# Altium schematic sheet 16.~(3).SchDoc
size 398 x 287 mm
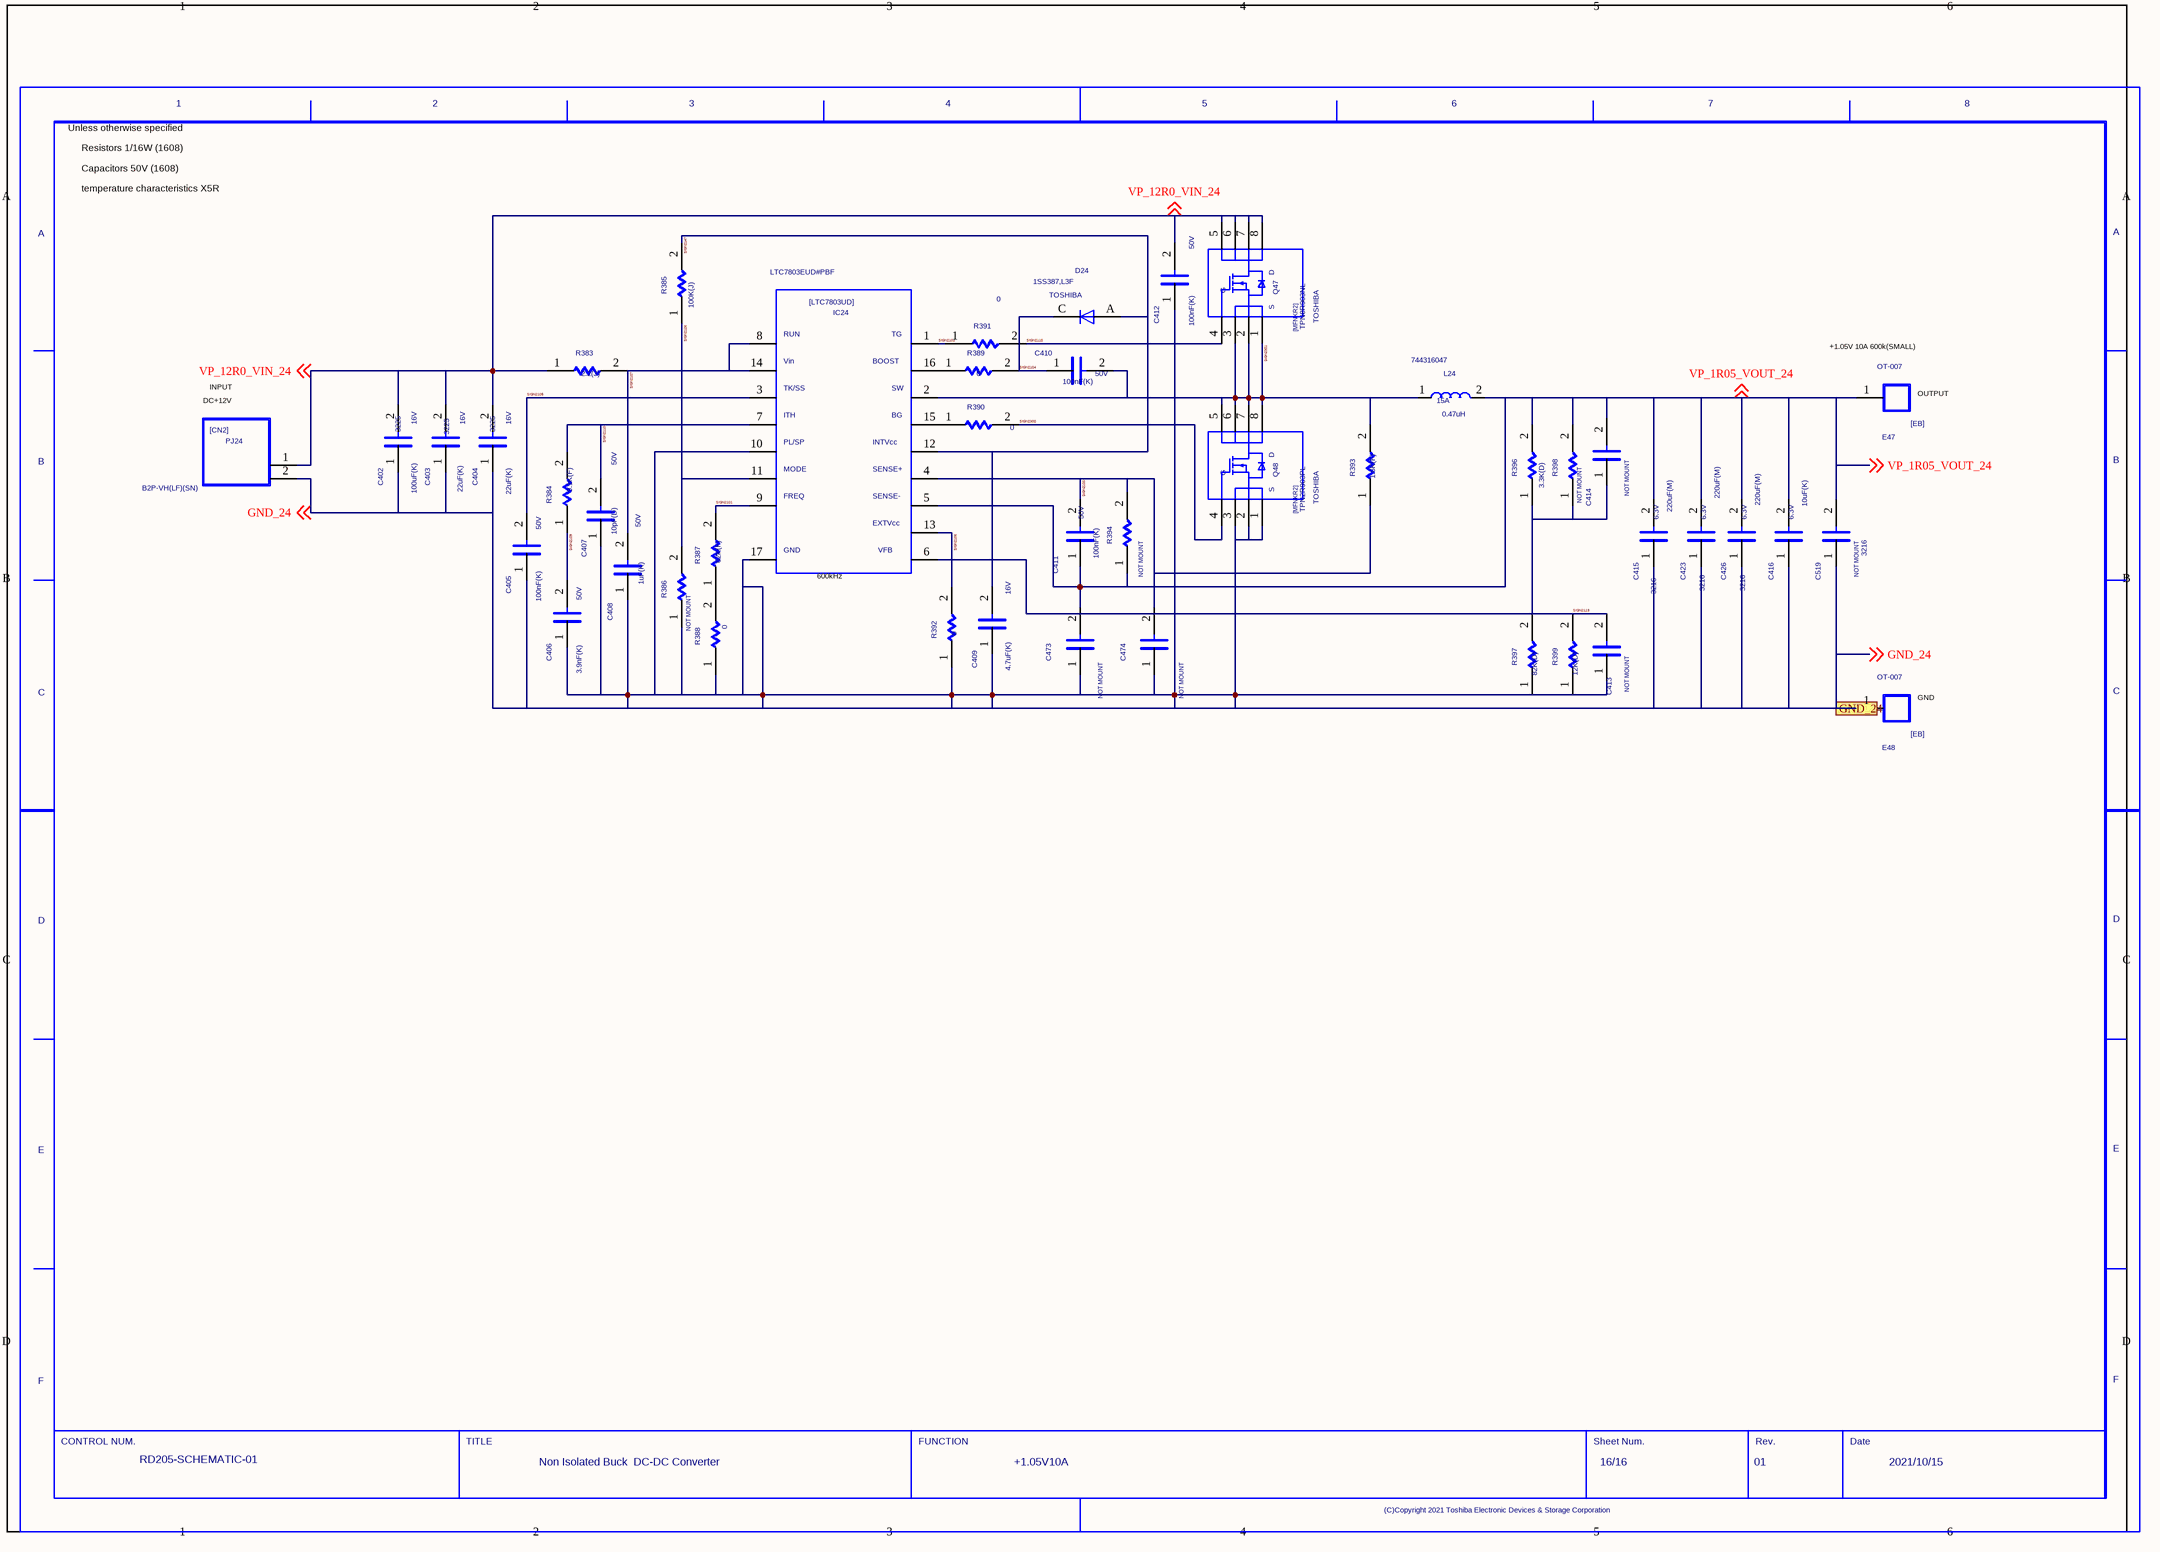
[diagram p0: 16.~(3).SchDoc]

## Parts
C402  SIZECODESMD: 3225  VAL2: 16V  VAL1: 100uF(K)  (hidden comment: C)
C403  SIZECODESMD: 3225  VAL2: 16V  VAL1: 22uF(K)  (hidden comment: C)
C404  SIZECODESMD: 3225  VAL2: 16V  VAL1: 22uF(K)  (hidden comment: C)
C405  VAL2: 50V  VAL1: 100nF(K)  (hidden comment: C)
C406  VAL2: 50V  VAL1: 3.9nF(K)  (hidden comment: C)
C407  VAL2: 50V  VAL1: 10pF(D)  (hidden comment: C)
C408  VAL2: 50V  VAL1: 1uF(K)  (hidden comment: C)
C409  VAL2: 16V  VAL1: 4.7uF(K)  (hidden comment: C)
C410  VAL2: 50V  VAL1: 100nF(K)  (hidden comment: C)
C411  VAL2: 50V  VAL1: 100nF(K)  (hidden comment: C)
C412  VAL2: 50V  VAL1: 100nF(K)  (hidden comment: C)
C413  NOTMOUNT: NOT MOUNT  (hidden comment: C)
C414  NOTMOUNT: NOT MOUNT  (hidden comment: C)
C415  SIZECODESMD: 3216  VAL2: 6.3V  VAL1: 220uF(M)  (hidden comment: C)
C416  VAL2: 6.3V  VAL1: 10uF(K)  (hidden comment: C)
C423  SIZECODESMD: 3216  VAL2: 6.3V  VAL1: 220uF(M)  (hidden comment: C)
C426  SIZECODESMD: 3216  VAL2: 6.3V  VAL1: 220uF(M)  (hidden comment: C)
C473  NOTMOUNT: NOT MOUNT  (hidden comment: C)
C474  NOTMOUNT: NOT MOUNT  (hidden comment: C)
C519  NOTMOUNT: NOT MOUNT  SIZECODESMD: 3216  (hidden comment: C)
D24  USERCOMPTEXT3: TOSHIBA  VAL3: 1SS387,L3F  (hidden comment: D)
E47  VAL3: OT-007  (hidden comment: EB)
E48  VAL3: OT-007  (hidden comment: EB)
IC24  VAL3: LTC7803EUD#PBF  (hidden comment: LTC7803UD)
L24  VAL3: 744316047  VAL2: 15A  VAL1: 0.47uH  (hidden comment: L)
PJ24  VAL3: B2P-VH(LF)(SN)  (hidden comment: CN2)
Q47  USERCOMPTEXT3: TOSHIBA  VAL3: TPN8R903NL  (hidden comment: MFNKR2)
Q48  USERCOMPTEXT3: TOSHIBA  VAL3: TPN2R903PL  (hidden comment: MFNKR2)
R383  VAL1: 2.2(J)  (hidden comment: R)
R384  VAL1: 9.1K(F)  (hidden comment: R)
R385  VAL1: 100K(J)  (hidden comment: R)
R386  NOTMOUNT: NOT MOUNT  (hidden comment: R)
R387  VAL1: 62K(F)  (hidden comment: R)
R388  VAL1: 0  (hidden comment: R)
R389  VAL1: 0  (hidden comment: R)
R390  VAL1: 0  (hidden comment: R)
R391  VAL1: 0  (hidden comment: R)
R392  VAL1: 0  (hidden comment: R)
R393  VAL1: 1.6K(F)  (hidden comment: R)
R394  NOTMOUNT: NOT MOUNT  (hidden comment: R)
R396  VAL1: 3.3K(D)  (hidden comment: R)
R397  VAL1: 82K(D)  (hidden comment: R)
R398  NOTMOUNT: NOT MOUNT  (hidden comment: R)
R399  VAL1: 12K(D)  (hidden comment: R)
U?  DATE: 2021/10/15  SHEETNUMBER: 16/16  TITLE: Non Isolated Buck / DC-DC Converter  REVISION: 01  DRAWINGNUMBER: RD205-SCHEMATIC-01  FUNCTION: +1.05V10A  (hidden comment: WAKU_DEF100)

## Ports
GND_24

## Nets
GND_24: C402.1 C403.1 C404.1 C405.1 C406.1 C407.1 C408.1 C409.1 C412.1 C413.1 C415.1 C416.1 C423.1 C426.1 C473.1 C474.1 C519.1 E48.1 IC24.10 IC24.17 PJ24.2 Q48.1 Q48.2 Q48.3 R386.1 R388.1 R392.1 R397.1 R399.1 ; off-sheet GND_24, port GND_24
SIGN2100: C411.2 C474.2 IC24.4 R393.1 R394.2
SIGN2101: IC24.9 R387.2
SIGN2103: IC24.1 R391.1
SIGN2104: C410.1 D24.C R389.2
SIGN2105: C405.2 IC24.3
SIGN2106: IC24.13 R392.2
SIGN2107: C408.2 IC24.8 IC24.14 R383.2
SIGN2109: C406.2 R384.1
SIGN2110: C407.2 IC24.7 R384.2
SIGN2113: C413.2 C414.1 IC24.6 R396.1 R397.2 R398.1 R399.2
SIGN2115: Q47.4 R391.2
SIGN2126: IC24.11 R385.1 R386.2
SIGN2147: C409.2 D24.A IC24.12 R385.2
SIGN2300: Q48.4 R390.2
SIGN2301: C410.2 IC24.2 L24.1 Q47.1 Q47.2 Q47.3 Q48.5 Q48.6 Q48.7 Q48.8 R393.2
VP_1R05_VOUT_24: C411.1 C414.2 C415.2 C416.2 C423.2 C426.2 C473.2 C519.2 E47.1 IC24.5 L24.2 R394.1 R396.2 R398.2 ; off-sheet VP_1R05_VOUT_24
VP_12R0_VIN_24: C402.2 C403.2 C404.2 C412.2 PJ24.1 Q47.5 Q47.6 Q47.7 Q47.8 R383.1 ; off-sheet VP_12R0_VIN_24
NetIC24_15: IC24.15 R390.1
NetIC24_16: IC24.16 R389.1
NetR387_1: R387.1 R388.2

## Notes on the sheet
- Unless otherwise specified
- Resistors 1/16W (1608)
- Capacitors 50V (1608)
- temperature characteristics X5R
- DC+12V
- INPUT
- (near E47) +1.05V 10A 600k(SMALL)
- (near E47) OUTPUT
- (near IC24) 600kHz
- (near E48) GND

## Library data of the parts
C402 = C: SQ_PART_MODEL: CON_100n; FNPARTSNAMEG: CHIP CERAMIC CAPACITOR (3225); USEINPARTSLIST: YES; OriginalSymbolOrigin: (2540,7620); MFSOLDERINGPROP: .; TEMPCHARACTERI2: B; MFFORMINGDIVP: KC; OUMECLASSIFICATION: セラミックコンデンサ; MFMOUNTSYMBOLP: 90; CDMASTERCADCELG: DC903A; PCODE: P03276001115; FNCLASSCODEG: P03-03; MAXGCOUNT: 1; RATEDVOLTAGE: 250; COMPONENTNAME: G36030160049; OUMEMAKER: KYC 京セラ; MFPACKAGEMETHOP: S; NOMINALCAPACITA: 100n; OUMEMAKERKATAMEI: CF32W5R104K250AT; CAPACITANCETOLE: K
C403 C404 = C: SQ_PART_MODEL: CON_22u; FNPARTSNAMEG: CHIP CERAMIC CAPACITOR (3225); USEINPARTSLIST: YES; OriginalSymbolOrigin: (2540,7620); MFSOLDERINGPROP: .; TEMPCHARACTERI2: B; MFFORMINGDIVP: KC; OUMECLASSIFICATION: セラミックコンデンサ; MFMOUNTSYMBOLP: 80; CDMASTERCADCELG: DC903A; PCODE: P03043035626; FNCLASSCODEG: P03-03; MAXGCOUNT: 1; RATEDVOLTAGE: 6.3; COMPONENTNAME: G36030119054; OUMEMAKER: TYD 太陽誘電; MFPACKAGEMETHOP: S; NOMINALCAPACITA: 22u; OUMEMAKERKATAMEI: JMK325BJ226KM-T; CAPACITANCETOLE: K
C405 C410 C412 = C: SQ_PART_MODEL: CON_100n; FNPARTSNAMEG: CHIP CERAMIC CAPACITOR (1608); USEINPARTSLIST: YES; OriginalSymbolOrigin: (2540,7620); MFSOLDERINGPROP: .; TEMPCHARACTERI2: B; MFFORMINGDIVP: KC; OUMECLASSIFICATION: セラミックコンデンサ; SIZECODESMD: 1608; MFMOUNTSYMBOLP: 80; CDMASTERCADCELG: C8100E; PCODE: P03B000000E4; FNCLASSCODEG: P03-03; MAXGCOUNT: 1; RATEDVOLTAGE: 16; COMPONENTNAME: GDM030000598; OUMEMAKER: MRT 村田製作所; MFPACKAGEMETHOP: S; NOMINALCAPACITA: 100n; OUMEMAKERKATAMEI: GRM188B11C104KA01C; CAPACITANCETOLE: K
C406 = C: SQ_PART_MODEL: CON_3.9n; FNPARTSNAMEG: CHIP CERAMIC CAPACITOR (1608); USEINPARTSLIST: YES; OriginalSymbolOrigin: (2540,7620); TOLERANCE: K; ASIMVALUE: 3.9N; MFSOLDERINGPROP: .; TEMPCHARACTERI2: B; MFFORMINGDIVP: KC; OUMECLASSIFICATION: セラミックコンデンサ; SIZECODESMD: 1608; MFMOUNTSYMBOLP: 80; CDMASTERCADCELG: C8100E; PCODE: P03039077227; FNCLASSCODEG: P03-03; MAXGCOUNT: 1; RATEDVOLTAGE: 50; COMPONENTNAME: G36030011242; OUMEMAKER: MRT 村田製作所; MFPACKAGEMETHOP: S; OUMEMAKERKATAMEI: GRM39B392K50PT
C407 = C: SQ_PART_MODEL: CON_10p; FNPARTSNAMEG: CHIP CERAMIC CAPACITOR (1608); USEINPARTSLIST: YES; OriginalSymbolOrigin: (2540,7620); TOLERANCE: D; ASIMVALUE: 10P; MFSOLDERINGPROP: .; TEMPCHARACTERI2: CH; MFFORMINGDIVP: KC; OUMECLASSIFICATION: セラミックコンデンサ; SIZECODESMD: 1608; MFMOUNTSYMBOLP: 80; CDMASTERCADCELG: C8100E; PCODE: P03039185229; FNCLASSCODEG: P03-03; MAXGCOUNT: 1; RATEDVOLTAGE: 50; COMPONENTNAME: G36030011013; OUMEMAKER: MRT 村田製作所; MFPACKAGEMETHOP: S; OUMEMAKERKATAMEI: GRM39CH100D50PT
C408 = C: SQ_PART_MODEL: CON_1u; FNPARTSNAMEG: CHIP CERAMIC CAPACITOR (1608); USEINPARTSLIST: YES; OriginalSymbolOrigin: (2540,7620); MFSOLDERINGPROP: .; TEMPCHARACTERI2: B; MFFORMINGDIVP: KC; OUMECLASSIFICATION: セラミックコンデンサ; SIZECODESMD: 1608; MFMOUNTSYMBOLP: 80; CDMASTERCADCELG: C8100E; PCODE: P03039ACE122; FNCLASSCODEG: P03-03; MAXGCOUNT: 1; RATEDVOLTAGE: 6.3; COMPONENTNAME: G36030104159; OUMEMAKER: KYC 京セラ; MFPACKAGEMETHOP: S; NOMINALCAPACITA: 1u; OUMEMAKERKATAMEI: CM105B105K06ATN; CAPACITANCETOLE: K
C409 = C: SQ_PART_MODEL: CON_4.7u; FNPARTSNAMEG: CHIP CERAMIC CAPACITOR (1608); USEINPARTSLIST: YES; OriginalSymbolOrigin: (2540,7620); MFSOLDERINGPROP: .; TEMPCHARACTERI2: B; MFFORMINGDIVP: KC; OUMECLASSIFICATION: セラミックコンデンサ; SIZECODESMD: 1608; MFMOUNTSYMBOLP: 80; CDMASTERCADCELG: C8100E; PCODE: P03B000000MS; FNCLASSCODEG: P03-03; MAXGCOUNT: 1; RATEDVOLTAGE: 4; COMPONENTNAME: GDM030000053; OUMEMAKER: KYC 京セラ; MFPACKAGEMETHOP: S; NOMINALCAPACITA: 4.7u; OUMEMAKERKATAMEI: CM105B475M04AT; CAPACITANCETOLE: M
C411 = C: SQ_PART_MODEL: CON_100n; FNPARTSNAMEG: CHIP CERAMIC CAPACITOR (1608); USEINPARTSLIST: YES; OriginalSymbolOrigin: (2540,7620); MFSOLDERINGPROP: .; TEMPCHARACTERI2: B; MFFORMINGDIVP: KC; OUMECLASSIFICATION: セラミックコンデンサ; SIZECODESMD: 1608; MFMOUNTSYMBOLP: 80; CDMASTERCADCELG: C8100E; PCODE: P03B000000E4; FNCLASSCODEG: P03-03; MAXGCOUNT: 1; RATEDVOLTAGE: 16; COMPONENTNAME: GDM030001129; OUMEMAKER: MRT 村田製作所; MFPACKAGEMETHOP: S; NOMINALCAPACITA: 100n; OUMEMAKERKATAMEI: GRM188B11C104KA01C; CAPACITANCETOLE: K
C413 C414 = C: SQ_PART_MODEL: CON_100p; FNPARTSNAMEG: CHIP CERAMIC CAPACITOR (1608); USEINPARTSLIST: YES; OriginalSymbolOrigin: (2540,7620); TOLERANCE: J; ASIMVALUE: 100P; MFSOLDERINGPROP: .; TEMPCHARACTERI2: CH; MFFORMINGDIVP: KC; OUMECLASSIFICATION: セラミックコンデンサ; SIZECODESMD: 1608; MFMOUNTSYMBOLP: 80; CDMASTERCADCELG: C8100E; PCODE: P03039177125; FNCLASSCODEG: P03-03; MAXGCOUNT: 1; RATEDVOLTAGE: 50; COMPONENTNAME: G36030011365; OUMEMAKER: KYC 京セラ; MFPACKAGEMETHOP: S; OUMEMAKERKATAMEI: CM105CH101J50AT; VAL2: 50V; VAL1: 100pF(J)
C415 C423 C426 = C: SQ_PART_MODEL: CON_22u; FNPARTSNAMEG: CHIP CERAMIC CAPACITOR (3216); USEINPARTSLIST: YES; OriginalSymbolOrigin: (2540,7620); MFSOLDERINGPROP: .; TEMPCHARACTERI2: B; MFFORMINGDIVP: KC; OUMECLASSIFICATION: セラミックコンデンサ; MFMOUNTSYMBOLP: 80; CDMASTERCADCELG: DC901A; PCODE: P03B0000004V; FNCLASSCODEG: P03-03; MAXGCOUNT: 1; RATEDVOLTAGE: 6.3; COMPONENTNAME: GDM030000020; OUMEMAKER: KYC 京セラ; MFPACKAGEMETHOP: S; NOMINALCAPACITA: 22u; OUMEMAKERKATAMEI: CM316B226M06AT; CAPACITANCETOLE: M
C416 = C: SQ_PART_MODEL: CON_1u; FNPARTSNAMEG: CHIP CERAMIC CAPACITOR (1608); PARTCOMMENT: 代表セル<KC0008> がフットプリントに登録されていません。; USEINPARTSLIST: YES; OriginalSymbolOrigin: (2540,7620); MFSOLDERINGPROP: .; TEMPCHARACTERI2: B; MFPACKAGEMETHOP: S; MFFORMINGDIVP: KC; MFMOUNTSYMBOLP: 80; PCODE: P03B000000ZQ; OUMECLASSIFICATION: セラミックコンデンサ; SIZECODESMD: 1608; CDMASTERCADCELG: KC0008; FNCLASSCODEG: P03-03; MAXGCOUNT: 1; RATEDVOLTAGE: 6.3; COMPONENTNAME: GDM030000202; OUMEMAKER: MRT 村田製作所; NOMINALCAPACITA: 1u; OUMEMAKERKATAMEI: GRM185B10J105KE21D; CAPACITANCETOLE: K
C473 C474 = C: SQ_PART_MODEL: CON_220n; FNPARTSNAMEG: CHIP CERAMIC CAPACITOR (1608); PARTCOMMENT: 代表セル<KC0008> がフットプリントに登録されていません。; USEINPARTSLIST: YES; OriginalSymbolOrigin: (2540,7620); MFSOLDERINGPROP: .; TEMPCHARACTERI2: B; MFFORMINGDIVP: KC; OUMECLASSIFICATION: セラミックコンデンサ; SIZECODESMD: 1608; MFMOUNTSYMBOLP: 80; CDMASTERCADCELG: KC0008; PCODE: P03B000001L3; FNCLASSCODEG: P03-03; MAXGCOUNT: 1; RATEDVOLTAGE: 16; COMPONENTNAME: GDM030001129; OUMEMAKER: MRT 村田製作所; MFPACKAGEMETHOP: S; NOMINALCAPACITA: 220n; OUMEMAKERKATAMEI: GRM188B11C224KA01D; VAL2: 16V; VAL1: 220nF(K); CAPACITANCETOLE: K
C519 = C: SQ_PART_MODEL: CON_22u; FNPARTSNAMEG: CHIP CERAMIC CAPACITOR (3216); USEINPARTSLIST: YES; OriginalSymbolOrigin: (2540,7620); MFSOLDERINGPROP: .; TEMPCHARACTERI2: B; MFFORMINGDIVP: KC; OUMECLASSIFICATION: セラミックコンデンサ; MFMOUNTSYMBOLP: 80; CDMASTERCADCELG: DC901A; PCODE: P03B0000004V; FNCLASSCODEG: P03-03; MAXGCOUNT: 1; RATEDVOLTAGE: 6.3; COMPONENTNAME: GDM030000020; OUMEMAKER: KYC 京セラ; MFPACKAGEMETHOP: S; NOMINALCAPACITA: 22u; OUMEMAKERKATAMEI: CM316B226M06AT; VAL2: 6.3V; VAL1: 22uF(M); CAPACITANCETOLE: M
D24 = D: FNPARTSNAMEG: DIODE; USEINPARTSLIST: YES; PARTNAME: GDM420000143; SAVEAREA0: -565,-171,12979,8058; SAVECOUNT: 1; TIME: 14:49:55; UPDATEUSER: 19870035; UPDATETIME: 14:20:16; OriginalSymbolOrigin: (5080,5080); FORWARDVOLTAGEM: 0; MAXREVERSEVOLTA: 80; COMPONENTNAME: GDM420000143_package; MFSOLDERINGPROP: .; OUMEMAKER: TSB 東芝（ＹＰＳＳ）; QUADMODEL: dummymodel; MFPACKAGEMETHOP: S; MFFORMINGDIVP: MM; MOUNTINGFORMSMD: SMD; OUMECLASSIFICATION: 小信号ダイオード; OUMEMAKERKATAMEI: 1SS387(TPH3,F); CDMASTERCADCELG: D8101D; PCODE: P42B0000008E; FNCLASSCODEG: P42-01
E47 E48 = EB: FNPARTSNAMEG: TERMINAL; USEINPARTSLIST: YES; PARTNAME: 5P9L1232P001; OUMEPARTTYPE: TB; OriginalSymbolOrigin: (2540,12700); COMPONENTNAME: 5P9L1232P001_package; MAXGCOUNT: 1; MFSOLDERINGPROP: .; OUMEMAKER: オサダ; QUADMODEL: dummymodel; MFPACKAGEMETHOP: I; MFFORMINGDIVP: OD; OUMECLASSIFICATION: 端子台、端子板; CDMASTERCADCELG: DE0009; KIND: PBS; PCODE: P29045001117; TERMINALSTYLE: SC; FNCLASSCODEG: P29-01
IC24 = LTC7803UD: USEINPARTSLIST: YES; SAVECOUNT: 29; SAVEAREA0: -53177,0,89020,58420; TIME: 16:14:14; UPDATEUSER: q91866sr; UPDATETIME: 13:15:36; OriginalSymbolOrigin: (5080,55880); MAXGCOUNT: 1; COMPONENTNAME: LTC7803UD_LTC7803UD; OUMEMAKER: ANALOG DEVICES
L24 = L: USEINPARTSLIST: YES; PARTNAME: 744316033; OriginalSymbolOrigin: (2540,5080); MAXGCOUNT: 1; COMPONENTNAME: L_L; OUMEMAKER: WURTH
PJ24 = CN2: FNPARTSNAMEG: 3.96PITCH NYLON CONNECTOR; USEINPARTSLIST: YES; PARTNAME: G36220114012; OUMEPARTTYPE: CN; OriginalSymbolOrigin: (2540,15240); MAXGCOUNT: 1; RATEDCURRENT: 7; COMPONENTNAME: G36220114012_package; MFSOLDERINGPROP: .; OUMEMAKER: JST 日本圧着端子製造; NUMBEROFCONTACT: 2; QUADMODEL: dummymodel; MFPACKAGEMETHOP: I; MFFORMINGDIVP: CU; CONTACTPITCH: 3.96m; OUMEMAKERKATAMEI: B2P-VH; CDMASTERCADCELG: DPJ514; PCODE: P22346001114; TERMINALSTYLE: PW; FNCLASSCODEG: P22-10
Q47 Q48 = MFNKR2: USEINPARTSLIST: YES; PARTNAME: TPN1R603PL; SAVEAREA0: -9199,-39,32138,22820; TIME: 18:57:44; UPDATEUSER: q91866sr; UPDATETIME: 12:36:02; SAVECOUNT: 10; OriginalSymbolOrigin: (5080,20320); MAXGCOUNT: 1; COMPONENTNAME: MFNKR2_MFNKR2
R383 = R: SQ_PART_MODEL: RES_2.2; FNPARTSNAMEG: CHIP RESISTOR (1608); USEINPARTSLIST: YES; OriginalSymbolOrigin: (5080,5080); TOLERANCE: J; ASIMVALUE: 2.2; MAXGCOUNT: 1; COMPONENTNAME: G36010011507; MFSOLDERINGPROP: .; OUMEMAKER: NAE 松下電子部品; MFPACKAGEMETHOP: S; MFFORMINGDIVP: KC; MOUNTINGFORMSMD: SMD; OUMECLASSIFICATION: 表面実装用固定抵抗器; MFMOUNTSYMBOLP: 80; POWERRATING: 63m; OUMEMAKERKATAMEI: ERJ3GEYJ2R2V; NUMBEROFELEMENT: 0; VAL2: 62.5mW; CDMASTERCADCELG: DR802R; PCODE: P01042157622; FNCLASSCODEG: P01-08
R384 = R: SQ_PART_MODEL: RES_9.1K; FNPARTSNAMEG: CHIP RESISTOR (1608); USEINPARTSLIST: YES; OriginalSymbolOrigin: (5080,5080); MAXGCOUNT: 1; COMPONENTNAME: G36010104414; MFSOLDERINGPROP: .; OUMEMAKER: HDK 北陸電気工業; MFPACKAGEMETHOP: S; MFFORMINGDIVP: KC; MOUNTINGFORMSMD: SMD; OUMECLASSIFICATION: 表面実装用固定抵抗器; RESISTANCETOLER: F; MFMOUNTSYMBOLP: 80; POWERRATING: 63m; OUMEMAKERKATAMEI: CR1/16 912FV; NOMINALRESISTAN: 9.1K; NUMBEROFELEMENT: 0; VAL2: 62.5mW; CDMASTERCADCELG: DR802R; PCODE: P01042501227; FNCLASSCODEG: P01-08
R385 = R: SQ_PART_MODEL: RES_100K; FNPARTSNAMEG: CHIP RESISTOR (1608); USEINPARTSLIST: YES; OriginalSymbolOrigin: (5080,5080); TOLERANCE: J; ASIMVALUE: 100K; MFSOLDERINGPROP: .; MFPACKAGEMETHOP: S; MFFORMINGDIVP: KC; MOUNTINGFORMSMD: SMD; MFMOUNTSYMBOLP: 80; NUMBEROFELEMENT: 0; PCODE: P01042047220; MAXGCOUNT: 1; COMPONENTNAME: G36010011057; OUMEMAKER: HDK 北陸電気工業; OUMECLASSIFICATION: 表面実装用固定抵抗器; POWERRATING: 63m; OUMEMAKERKATAMEI: CR1/16 104JV; VAL2: 62.5mW; CDMASTERCADCELG: DR802R; FNCLASSCODEG: P01-08
R386 = R: SQ_PART_MODEL: RES_10; FNPARTSNAMEG: CHIP RESISTOR (1608); USEINPARTSLIST: YES; OriginalSymbolOrigin: (5080,5080); TOLERANCE: F; ASIMVALUE: 10; MFSOLDERINGPROP: .; MFPACKAGEMETHOP: S; MFFORMINGDIVP: KC; MOUNTINGFORMSMD: SMD; MFMOUNTSYMBOLP: 80; NUMBEROFELEMENT: 0; PCODE: P01042036620; MAXGCOUNT: 1; COMPONENTNAME: G36010104063; OUMEMAKER: NAE 松下電子部品; OUMECLASSIFICATION: 表面実装用固定抵抗器; POWERRATING: 63m; OUMEMAKERKATAMEI: ERJ3GEYF100V; VAL2: 62.5mW; VAL1: 10(F); CDMASTERCADCELG: DR802R; FNCLASSCODEG: P01-08
R387 = R: SQ_PART_MODEL: RES_62K; FNPARTSNAMEG: CHIP RESISTOR (1608); USEINPARTSLIST: YES; OriginalSymbolOrigin: (5080,5080); MAXGCOUNT: 1; COMPONENTNAME: GDM010001037; MFSOLDERINGPROP: .; OUMEMAKER: NAE 松下電子部品; MFPACKAGEMETHOP: S; MFFORMINGDIVP: KC; MOUNTINGFORMSMD: SMD; OUMECLASSIFICATION: 表面実装用固定抵抗器; RESISTANCETOLER: F; MFMOUNTSYMBOLP: 80; POWERRATING: 63m; OUMEMAKERKATAMEI: ERJ3GEYF623V; NOMINALRESISTAN: 62K; NUMBEROFELEMENT: 0; VAL2: 62.5mW; CDMASTERCADCELG: DR802R; PCODE: P01042441622; FNCLASSCODEG: P01-08
R388 = R: SQ_PART_MODEL: RES_160K; FNPARTSNAMEG: CHIP RESISTOR (1608); USEINPARTSLIST: YES; OriginalSymbolOrigin: (5080,5080); MAXGCOUNT: 1; COMPONENTNAME: G51011061108; MFSOLDERINGPROP: .; OUMEMAKER: HDK 北陸電気工業; MFPACKAGEMETHOP: S; MFFORMINGDIVP: KC; MOUNTINGFORMSMD: SMD; OUMECLASSIFICATION: 表面実装用固定抵抗器; RESISTANCETOLER: F; MFMOUNTSYMBOLP: 80; POWERRATING: 63m; OUMEMAKERKATAMEI: CR1/16 164FV; NOMINALRESISTAN: 160K; VAL2: 62.5mW; CDMASTERCADCELG: DR802R; PCODE: P01042125225; FNCLASSCODEG: P01-08
R389 R392 = R: SQ_PART_MODEL: RES_10; FNPARTSNAMEG: CHIP RESISTOR (1608); USEINPARTSLIST: YES; OriginalSymbolOrigin: (5080,5080); TOLERANCE: F; ASIMVALUE: 10; MFSOLDERINGPROP: .; MFPACKAGEMETHOP: S; MFFORMINGDIVP: KC; MOUNTINGFORMSMD: SMD; MFMOUNTSYMBOLP: 80; PCODE: P01042036620; MAXGCOUNT: 1; COMPONENTNAME: G36010104063; OUMEMAKER: NAE 松下電子部品; OUMECLASSIFICATION: 表面実装用固定抵抗器; POWERRATING: 63m; OUMEMAKERKATAMEI: ERJ3GEYF100V; VAL2: 62.5mW; CDMASTERCADCELG: DR802R; FNCLASSCODEG: P01-08
R390 R391 = R: SQ_PART_MODEL: RES_10; FNPARTSNAMEG: CHIP RESISTOR (2012); USEINPARTSLIST: YES; OriginalSymbolOrigin: (5080,5080); MAXGCOUNT: 1; TOLERANCE: F; COMPONENTNAME: 5P9L1083P100; MFSOLDERINGPROP: .; OUMEMAKER: 北陸電気工業; MFPACKAGEMETHOP: S; MFFORMINGDIVP: KC; MOUNTINGFORMSMD: SMD; OUMECLASSIFICATION: 表面実装用固定抵抗器; ASIMVALUE: 10; MFMOUNTSYMBOLP: 90; POWERRATING: 100m; OUMEMAKERKATAMEI: CR1/10 100FV Pb(F); VAL2: 125mW; CDMASTERCADCELG: DR910A; PCODE: P01043091222; FNCLASSCODEG: P01-08
R393 = R: SQ_PART_MODEL: RES_1.6K; FNPARTSNAMEG: CHIP RESISTOR (1608); USEINPARTSLIST: YES; OriginalSymbolOrigin: (5080,5080); MAXGCOUNT: 1; COMPONENTNAME: G51011055107; MFSOLDERINGPROP: .; OUMEMAKER: HDK 北陸電気工業; MFPACKAGEMETHOP: S; MFFORMINGDIVP: KC; MOUNTINGFORMSMD: SMD; OUMECLASSIFICATION: 表面実装用固定抵抗器; RESISTANCETOLER: F; MFMOUNTSYMBOLP: 80; POWERRATING: 63m; OUMEMAKERKATAMEI: CR1/16 162FV; NOMINALRESISTAN: 1.6K; NUMBEROFELEMENT: 0; VAL2: 62.5mW; CDMASTERCADCELG: DR802R; PCODE: P01042026225; FNCLASSCODEG: P01-08
R394 = R: SQ_PART_MODEL: RES_68K; FNPARTSNAMEG: CHIP RESISTOR (1608); USEINPARTSLIST: YES; OriginalSymbolOrigin: (5080,5080); MAXGCOUNT: 1; COMPONENTNAME: G36010027126; OUMEMAKER: HDK 北陸電気工業; MOUNTINGFORMSMD: SMD; OUMECLASSIFICATION: 表面実装用固定抵抗器; RESISTANCETOLER: F; POWERRATING: 63m; OUMEMAKERKATAMEI: CR1/16 683FV; NOMINALRESISTAN: 68K; CDMASTERCADCELG: DR802R; MFSOLDERINGPROP: .; MFPACKAGEMETHOP: S; MFFORMINGDIVP: KC; MFMOUNTSYMBOLP: 80; NUMBEROFELEMENT: 0; VAL2: 62.5mW; VAL1: 68K(F); PCODE: P01042456220; FNCLASSCODEG: P01-08
R396 = R: SQ_PART_MODEL: RES_3.3K; FNPARTSNAMEG: CHIP RESISTOR (1608); USEINPARTSLIST: YES; OriginalSymbolOrigin: (5080,5080); MAXGCOUNT: 1; COMPONENTNAME: G36010014485; MFSOLDERINGPROP: .; OUMEMAKER: SSM 進工業; MFPACKAGEMETHOP: S; MFFORMINGDIVP: KC; MOUNTINGFORMSMD: SMD; OUMECLASSIFICATION: 表面実装用固定抵抗器; RESISTANCETOLER: D; MFMOUNTSYMBOLP: 80; POWERRATING: 63m; OUMEMAKERKATAMEI: RR0816P-332-D; NOMINALRESISTAN: 3.3K; NUMBEROFELEMENT: 0; VAL2: 62.5mW; CDMASTERCADCELG: DR802R; PCODE: P01042249822; FNCLASSCODEG: P01-08
R397 = R: ICX_PART_MODEL: RES_82K; FNPARTSNAMEG: CHIP RESISTOR (1608); OriginalSymbolOrigin: (5080,5080); FNCLASSCODEG: P01-08; PCODE: P01042604621; CDMASTERCADCELG: DR802R; USEWITHSCHEMA: YES; VAL2: 62.5mW; NUMBEROFELEMENT: 0; NOMINALRESISTAN: 82K; OUMEMAKERKATAMEI: ERA3YKD823V; POWERRATING: 63m; MFMOUNTSYMBOLP: 80; RESISTANCETOLER: D; FUNCTION: G36010014829; OUMECLASSIFICATION: 表面実装用固定抵抗器; MOUNTINGFORMSMD: SMD; MFFORMINGDIVP: KC; MFPACKAGEMETHOP: S; OUMEMAKER: NAE 松下電子部品; MFSOLDERINGPROP: .; MAXGCOUNT: 1
R398 = R: SQ_PART_MODEL: RES_3.3K; FNPARTSNAMEG: CHIP RESISTOR (1608); USEINPARTSLIST: YES; OriginalSymbolOrigin: (5080,5080); TOLERANCE: F; ASIMVALUE: 3.3K; MAXGCOUNT: 1; COMPONENTNAME: G36010027027; MFSOLDERINGPROP: .; OUMEMAKER: ROH ロー・; MFPACKAGEMETHOP: S; MFFORMINGDIVP: KC; MOUNTINGFORMSMD: SMD; OUMECLASSIFICATION: 表面実装用固定抵抗器; MFMOUNTSYMBOLP: 80; POWERRATING: 63m; OUMEMAKERKATAMEI: MCR03EZPFX3301; NUMBEROFELEMENT: 0; VAL2: 62.5mW; VAL1: 3.3K(F); CDMASTERCADCELG: DR802R; PCODE: P01042250729; FNCLASSCODEG: P01-08
R399 = R: ICX_PART_MODEL: RES_12K; FNPARTSNAMEG: CHIP RESISTOR (1608); OriginalSymbolOrigin: (5080,5080); FNCLASSCODEG: P01-08; PCODE: P01117055112; CDMASTERCADCELG: DR802R; USEWITHSCHEMA: YES; VAL2: 62.5mW; NUMBEROFELEMENT: 0; NOMINALRESISTAN: 12K; OUMEMAKERKATAMEI: RK73G1JTD123D; POWERRATING: 63m; MFMOUNTSYMBOLP: 80; RESISTANCETOLER: D; FUNCTION: G36010129516; OUMECLASSIFICATION: 表面実装用固定抵抗器; MOUNTINGFORMSMD: SMD; MFFORMINGDIVP: KC; MFPACKAGEMETHOP: S; OUMEMAKER: KOA ＫＯＡ; MFSOLDERINGPROP: .; MAXGCOUNT: 1
U? = WAKU_DEF100: PLOTTIME: HH:MM; SAVEAREA0: 330961,54,387907,31546; TIME: 19:23:07; UPDATEUSER: t5459927; UPDATETIME: 15:33:43; SAVECOUNT: 6; OriginalSymbolOrigin: (10160,284480); DESIGNED: ***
